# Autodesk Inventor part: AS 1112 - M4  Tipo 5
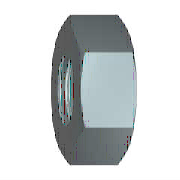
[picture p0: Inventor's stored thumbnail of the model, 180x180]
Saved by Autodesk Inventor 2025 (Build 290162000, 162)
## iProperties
Created: 2024-01
Part Number: AS 1112 - M4  Tipo 5
Material: Acciaio, Dolce
Description: Dadi esagonali metrici ISO, inclusi dadi sottili, dadi con intaglio e dadi a corona
Document SubType Name: Modeling
Standard: AS 1112
Designer: 18907419
Standards Organization: AS
Language: it-IT
Size Designation: M4  Tipo 5
Categories: <MemberInstance><Categories><Category DisplayName="Elementi di fissaggio" InternalName="e4da775c-781d-43d5-af7c-5136215cf5a6" Mnemonic="FSTN"><Category DisplayN
Density: 7.85 g/cm^3
Appearance: Semilucidato
IsCustomPart: 0
Author: 18907419
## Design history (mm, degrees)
body "Solid1"
workaxis "Work Axis1"
workplane "Work Plane1"
sketch "Schizzo1"
  geometry: L1 (-4.041, 0)-(-2.021, 3.5); L2 (-2.021, 3.5)-(2.021, 3.5); L3 (2.021, 3.5)-(4.041, 0); L4 (4.041, 0)-(2.021, -3.5); L5 (2.021, -3.5)-(-2.021, -3.5); L6 (-2.021, -3.5)-(-4.041, 0); 2 further points
  constraints: 12 end point, 1 coincident, 1 horizontal, 11 other
  dimensions: "d0" = 8.0829 distance of L3.end L1.start (= 1.1547 x SW)
extrude "Corpo" new body sketch "Schizzo1" distance "d1" = 3.2 (= KOH); taper "d2" = 0 deg
revolve "Smusso1" stored, may be unused: angle "d7" = 90 deg
sketch "Schizzo3"
  geometry: A1 r 3.5 centre (0, 0) between (-1.75, -3.031) and (1.75, -3.031) reference; 1 further point
  constraints: 1 coincident
hole "Filettatura" sketch "Schizzo3" diameter "d25" = 3.242; stored, may be unused: countersink angle "d29" = 82 deg, drill point angle "d31" = 118 deg; dims "d26" = 6, "d27" = 4, "d28" = 2, "d30" = 8
chamfer "Smusso2" distance "d8" = 0.37889 (= -0.5 x GD1 + 0.5 x NND); stored, may be unused: angle "d9" = 30 deg, second distance "d40" = 0.37889 (= -0.5 x GD1 + 0.5 x NND)
chamfer "Smusso3" distance "d10" = 0.37889 (= -0.5 x GD1 + 0.5 x NND); stored, may be unused: angle "d11" = 30 deg, second distance "d41" = 0.37889 (= -0.5 x GD1 + 0.5 x NND)
sketch "Schizzo2"
  geometry: L1 (0, 2.021)-(0, 4.041) reference; L2 (0, 4.041)-(3.2, 4.041) reference; L3 (3.2, 2.021)-(3.2, 4.041) reference; L4 (-0.64, 0)-(3.84, 0) reference; L5 (0.313, 4.041)-(0, 3.5); L6 (2.887, 4.041)-(3.2, 3.5)
  constraints: 4 end point, 4 point on line
  dimensions: "d3" = 30 deg angle of L1 L5 (= ANG1); "d4" = 30 deg angle of L3 L6 (= ANG2); "d5" = 7 diameter of L5.end L4 (= SW0); "d6" = 7 diameter of L6.end L4 (= SW01)
other parameters: "ANG1" = 30 deg [user parameter; used in 1 equation term], "ANG2" = 30 deg [user parameter; used in 1 equation term], "NND" = 4 [user parameter; used in 4 equation terms], "KOH" = 3.2 [user parameter; used in 1 equation term], "SW" = 7 [user parameter; used in 4 equation terms], "SW0" = 7 (= SW) [user parameter; used in 1 equation term], "SW01" = 7 (= SW) [user parameter; used in 1 equation term], "GD1" = 3.24223 (computed from THREADDIA, PTC, TOA) [user parameter; used in 4 equation terms], "d13" = 0, "d14" = 0, "d39" = 0, "d42" = 0, "GUL" = 0.37889 (= 0.541266 x PTC) [user parameter], "TPU" = 14.28571 (computed from PTC) [user parameter], "WFT" = 0.4 [user parameter], "THREADDIA" = 4 [user parameter; used in 1 equation term], "TOA" = 30 deg [user parameter; used in 1 equation term], "PTC" = 0.7 [user parameter; used in 4 equation terms], "E0" = 8.085 (= 1.155 x SW) [user parameter], "GAL" = 0.37889 (= 0.541266 x PTC) [user parameter]
